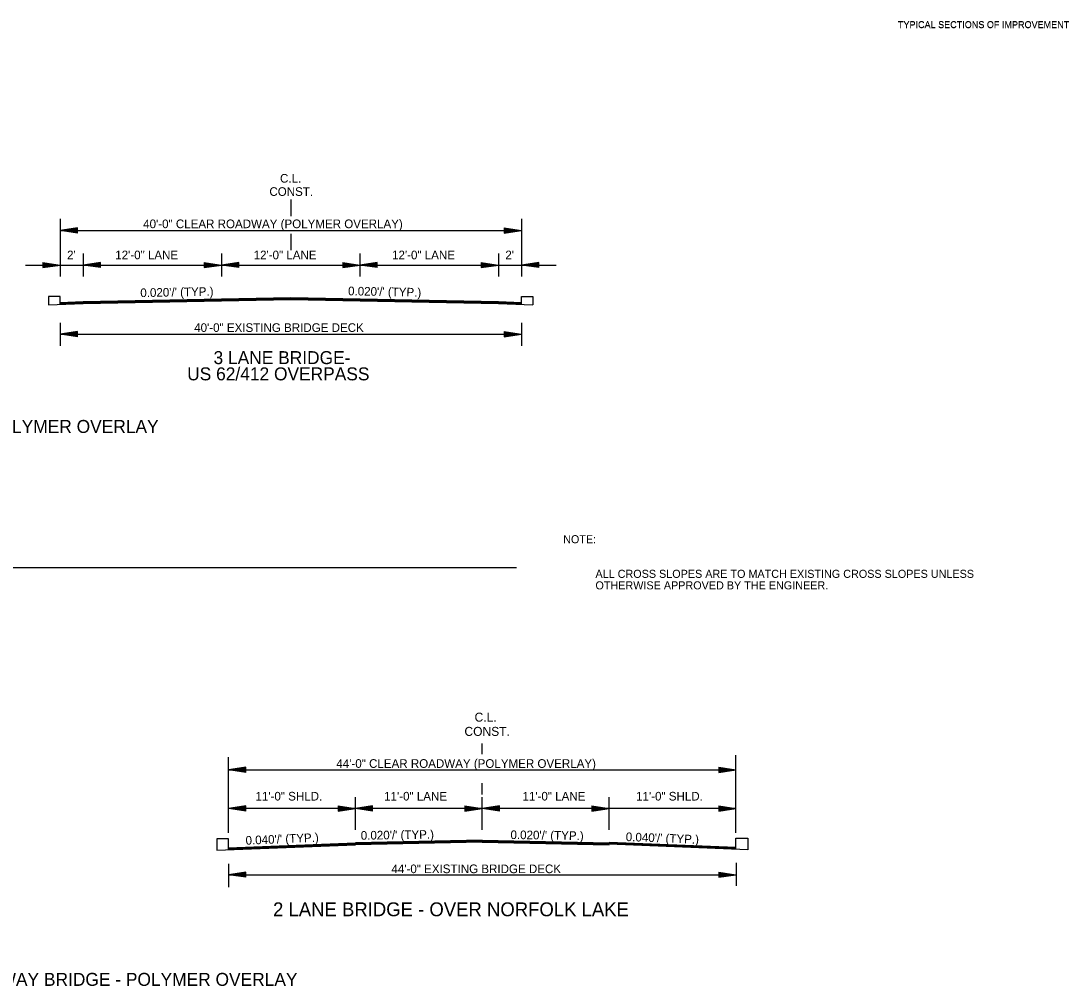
# Model space of a CAD drawing. Extents: x 550980 to 1930787, y -1972975 to 596640.
# Drawn here: x 551625 to 552533, y -1970315 to -1969477 of the extents above; entities that cross this region are included whole.
import ezdxf

# ---------------------------------------------------------------- set-up
doc = ezdxf.new("R2010")
doc.units = 0
for name, color, linetype in [('R_Border', 7, 'Continuous'), ('R_Border Notes', 7, 'Continuous'), ('R_Draft', 7, 'Continuous'), ('S_AREA_CALC', 7, 'Continuous')]:
    doc.layers.add(name, color=color, linetype=linetype)

# ---------------------------------------------------------------- blocks, each defined once
blk = doc.blocks.new('ARROW')
at = {"layer": 'R_Draft'}
for p, q in [((-2, 0.3), (0, 0)), ((-2, 0.3), (-2, -0.3)), ((-2, 0.25), (-0.334, 0)), ((-2, 0.199), (-0.678, 0)), ((-2, 0.149), (-1.011, 0)), ((-2, 0.097), (-1.35, 0)), ((-2, 0.047), (-1.684, 0)), ((-2, -0.3), (0, 0)), ((-2, -0.098), (-1.35, 0)), ((-2, -0.199), (-0.678, 0)), ((-2, -0.25), (-0.334, 0)), ((-2, -0.149), (-1.011, 0)), ((-2, -0.047), (-1.684, 0))]:
    blk.add_line(p, q, dxfattribs=at)

msp = doc.modelspace()

# ---------------------------------------------------------------- linework, layer by layer
at = {"layer": 'R_Border'}
for p, q in [((551858.45, -1969632.14), (551858.45, -1969646.64)), ((551658.45, -1969649.14), (551658.45, -1969699.14)), ((552058.45, -1969649.14), (552058.45, -1969699.14)), ((551658.45, -1969659.14), (552058.45, -1969659.14)), ((551858.45, -1969662.14), (551858.45, -1969676.14)), ((551678.45, -1969679.14), (551678.45, -1969699.14)), ((551798.45, -1969679.14), (551798.45, -1969699.14)), ((551918.45, -1969679.14), (551918.45, -1969699.14)), ((552038.45, -1969679.14), (552038.45, -1969699.14)), ((551628.45, -1969689.14), (552088.45, -1969689.14)), ((551658.45, -1969739.14), (551658.45, -1969759.14)), ((552058.45, -1969739.14), (552058.45, -1969759.14)), ((551658.45, -1969749.14), (552058.45, -1969749.14)), ((550992.91, -1969951.43), (552054.18, -1969951.43)), ((551804.45, -1970186.75), (551794.28, -1970186.75)), ((551794.28, -1970186.75), (551794.28, -1970196.79)), ((551804.45, -1970196.19), (551804.45, -1970186.75)), ((552244.45, -1970195.79), (552244.45, -1970186.35)), ((552244.45, -1970186.35), (552254.62, -1970186.35)), ((552254.62, -1970186.35), (552254.61, -1970196.39))]:
    msp.add_line(p, q, dxfattribs=at)
for points in [[(551658.45, -1969723.04), (551658.45, -1969716.54), (551648.45, -1969716.54), (551648.45, -1969723.74)], [(551648.45, -1969723.74), (551678.45, -1969722.54), (551858.45, -1969718.94), (552038.45, -1969722.54), (552068.45, -1969723.74)], [(551658.45, -1969721.54), (551678.45, -1969720.74), (551858.45, -1969717.14), (552038.45, -1969720.74), (552058.45, -1969721.54)], [(551658.45, -1969721.84), (551678.45, -1969721.04), (551858.45, -1969717.44), (552038.45, -1969721.04), (552058.45, -1969721.84)], [(551658.45, -1969722.14), (551678.45, -1969721.34), (551858.45, -1969717.74), (552038.45, -1969721.34), (552058.45, -1969722.14)], [(551658.45, -1969722.44), (551678.45, -1969721.64), (551858.45, -1969718.04), (552038.45, -1969721.64), (552058.45, -1969722.44)], [(551658.45, -1969722.74), (551678.45, -1969721.94), (551858.45, -1969718.34), (552038.45, -1969721.94), (552058.45, -1969722.74)], [(551658.45, -1969723.04), (551678.45, -1969722.24), (551858.45, -1969718.64), (552038.45, -1969722.24), (552058.45, -1969723.04)], [(552058.45, -1969723.04), (552058.45, -1969716.54), (552068.45, -1969716.54), (552068.45, -1969723.74)]]:
    msp.add_lwpolyline(points, dxfattribs=at)
at = {"layer": 'R_Draft'}
for p, q in [((552024.45, -1970113.53), (552024.45, -1970104.22)), ((551804.45, -1970181.63), (551804.45, -1970116.12)), ((552244.45, -1970181.63), (552244.45, -1970114.36)), ((551819.45, -1970124.69), (551804.45, -1970126.94)), ((551804.45, -1970126.94), (552244.45, -1970126.94)), ((551819.45, -1970129.19), (551804.45, -1970126.94)), ((551819.45, -1970125.07), (551806.96, -1970126.94)), ((551819.45, -1970128.82), (551806.96, -1970126.94)), ((551819.45, -1970125.45), (551809.54, -1970126.94)), ((551819.45, -1970128.43), (551809.54, -1970126.94)), ((551819.45, -1970125.82), (551812.03, -1970126.94)), ((551819.45, -1970128.06), (551812.03, -1970126.94)), ((551819.45, -1970126.21), (551814.58, -1970126.94)), ((551819.45, -1970127.67), (551814.58, -1970126.94)), ((551819.45, -1970126.59), (551817.08, -1970126.94)), ((551819.45, -1970127.29), (551817.08, -1970126.94)), ((551819.45, -1970129.19), (551819.45, -1970124.69)), ((552229.45, -1970124.69), (552244.45, -1970126.94)), ((552229.45, -1970124.69), (552229.45, -1970129.19)), ((552229.45, -1970125.07), (552241.95, -1970126.94)), ((552229.45, -1970125.45), (552239.37, -1970126.94)), ((552229.45, -1970125.82), (552236.87, -1970126.94)), ((552229.45, -1970126.21), (552234.33, -1970126.94)), ((552229.45, -1970126.59), (552231.82, -1970126.94)), ((552229.45, -1970129.19), (552244.45, -1970126.94)), ((552229.45, -1970127.68), (552234.33, -1970126.94)), ((552229.45, -1970128.43), (552239.37, -1970126.94)), ((552229.45, -1970128.82), (552241.95, -1970126.94)), ((552229.45, -1970128.06), (552236.87, -1970126.94)), ((552229.45, -1970127.29), (552231.82, -1970126.94)), ((552024.45, -1970148.46), (552024.45, -1970138.59)), ((551914.45, -1970179.14), (551914.45, -1970150.59)), ((552024.45, -1970179.14), (552024.45, -1970150.59)), ((552134.45, -1970179.14), (552134.45, -1970150.59)), ((551819.45, -1970158.23), (551804.45, -1970160.48)), ((551914.45, -1970160.48), (551804.45, -1970160.48)), ((551819.45, -1970162.73), (551804.45, -1970160.48)), ((551819.45, -1970158.6), (551806.96, -1970160.48)), ((551819.45, -1970162.35), (551806.96, -1970160.48)), ((551819.45, -1970158.99), (551809.54, -1970160.48)), ((551819.45, -1970161.97), (551809.54, -1970160.48)), ((551819.45, -1970159.36), (551812.03, -1970160.48)), ((551819.45, -1970161.6), (551812.03, -1970160.48)), ((551819.45, -1970159.74), (551814.58, -1970160.48)), ((551819.45, -1970161.21), (551814.58, -1970160.48)), ((551819.45, -1970160.13), (551817.08, -1970160.48)), ((551819.45, -1970160.83), (551817.08, -1970160.48)), ((551819.45, -1970162.73), (551819.45, -1970158.23)), ((551899.45, -1970158.23), (551914.45, -1970160.48)), ((551899.45, -1970158.23), (551899.45, -1970162.73)), ((551899.45, -1970158.6), (551911.95, -1970160.48)), ((551899.45, -1970158.99), (551909.37, -1970160.48)), ((551899.45, -1970159.36), (551906.87, -1970160.48)), ((551899.45, -1970159.75), (551904.33, -1970160.48)), ((551899.45, -1970160.13), (551901.82, -1970160.48)), ((551899.45, -1970162.73), (551914.45, -1970160.48)), ((551899.45, -1970161.21), (551904.33, -1970160.48)), ((551899.45, -1970161.97), (551909.37, -1970160.48)), ((551899.45, -1970162.35), (551911.95, -1970160.48)), ((551899.45, -1970161.6), (551906.87, -1970160.48)), ((551899.45, -1970160.83), (551901.82, -1970160.48)), ((551929.45, -1970158.23), (551914.45, -1970160.48)), ((552024.45, -1970160.48), (551914.45, -1970160.48)), ((551929.45, -1970162.73), (551914.45, -1970160.48)), ((551929.45, -1970158.6), (551916.96, -1970160.48)), ((551929.45, -1970162.35), (551916.96, -1970160.48)), ((551929.45, -1970158.99), (551919.54, -1970160.48)), ((551929.45, -1970161.97), (551919.54, -1970160.48)), ((551929.45, -1970159.36), (551922.03, -1970160.48)), ((551929.45, -1970161.6), (551922.03, -1970160.48)), ((551929.45, -1970159.74), (551924.58, -1970160.48)), ((551929.45, -1970161.21), (551924.58, -1970160.48)), ((551929.45, -1970160.13), (551927.08, -1970160.48)), ((551929.45, -1970160.83), (551927.08, -1970160.48)), ((551929.45, -1970162.73), (551929.45, -1970158.23)), ((552009.45, -1970158.23), (552024.45, -1970160.48)), ((552009.45, -1970158.23), (552009.45, -1970162.73)), ((552009.45, -1970158.6), (552021.95, -1970160.48)), ((552009.45, -1970158.99), (552019.37, -1970160.48)), ((552009.45, -1970159.36), (552016.87, -1970160.48)), ((552009.45, -1970159.75), (552014.33, -1970160.48)), ((552009.45, -1970160.13), (552011.82, -1970160.48)), ((552009.45, -1970162.73), (552024.45, -1970160.48)), ((552009.45, -1970161.21), (552014.33, -1970160.48)), ((552009.45, -1970161.97), (552019.37, -1970160.48)), ((552009.45, -1970162.35), (552021.95, -1970160.48)), ((552009.45, -1970161.6), (552016.87, -1970160.48)), ((552009.45, -1970160.83), (552011.82, -1970160.48)), ((552039.45, -1970158.23), (552024.45, -1970160.48)), ((552134.45, -1970160.48), (552024.45, -1970160.48)), ((552039.45, -1970162.73), (552024.45, -1970160.48)), ((552039.45, -1970158.6), (552026.96, -1970160.48)), ((552039.45, -1970162.35), (552026.96, -1970160.48)), ((552039.45, -1970158.99), (552029.54, -1970160.48)), ((552039.45, -1970161.97), (552029.54, -1970160.48)), ((552039.45, -1970159.36), (552032.03, -1970160.48)), ((552039.45, -1970161.6), (552032.03, -1970160.48)), ((552039.45, -1970159.74), (552034.58, -1970160.48)), ((552039.45, -1970161.21), (552034.58, -1970160.48)), ((552039.45, -1970160.13), (552037.08, -1970160.48)), ((552039.45, -1970160.83), (552037.08, -1970160.48)), ((552039.45, -1970162.73), (552039.45, -1970158.23)), ((552119.45, -1970158.23), (552134.45, -1970160.48)), ((552119.45, -1970158.23), (552119.45, -1970162.73)), ((552119.45, -1970158.6), (552131.95, -1970160.48)), ((552119.45, -1970158.99), (552129.37, -1970160.48)), ((552119.45, -1970159.36), (552126.87, -1970160.48)), ((552119.45, -1970159.75), (552124.33, -1970160.48)), ((552119.45, -1970160.13), (552121.82, -1970160.48)), ((552119.45, -1970162.73), (552134.45, -1970160.48)), ((552119.45, -1970161.21), (552124.33, -1970160.48)), ((552119.45, -1970161.97), (552129.37, -1970160.48)), ((552119.45, -1970162.35), (552131.95, -1970160.48)), ((552119.45, -1970161.6), (552126.87, -1970160.48)), ((552119.45, -1970160.83), (552121.82, -1970160.48)), ((552244.45, -1970160.48), (552134.45, -1970160.48)), ((552229.45, -1970158.23), (552244.45, -1970160.48)), ((552229.45, -1970158.23), (552229.45, -1970162.73)), ((552229.45, -1970158.6), (552241.95, -1970160.48)), ((552229.45, -1970158.99), (552239.37, -1970160.48)), ((552229.45, -1970159.36), (552236.87, -1970160.48)), ((552229.45, -1970159.75), (552234.33, -1970160.48)), ((552229.45, -1970160.13), (552231.82, -1970160.48)), ((552229.45, -1970162.73), (552244.45, -1970160.48)), ((552229.45, -1970161.21), (552234.33, -1970160.48)), ((552229.45, -1970161.97), (552239.37, -1970160.48)), ((552229.45, -1970162.35), (552241.95, -1970160.48)), ((552229.45, -1970161.6), (552236.87, -1970160.48)), ((552229.45, -1970160.83), (552231.82, -1970160.48)), ((551794.28, -1970196.79), (551914.45, -1970191.99)), ((551804.45, -1970194.69), (551914.45, -1970190.29)), ((551804.45, -1970194.99), (551914.45, -1970190.59)), ((551804.45, -1970195.29), (551914.45, -1970190.89)), ((551804.45, -1970195.59), (551914.45, -1970191.19)), ((551804.45, -1970195.89), (551914.45, -1970191.49)), ((551804.45, -1970196.19), (551914.45, -1970191.79)), ((552024.45, -1970188.09), (551914.45, -1970190.29)), ((552024.46, -1970188.39), (551914.45, -1970190.59)), ((552024.46, -1970188.69), (551914.45, -1970190.89)), ((552024.47, -1970188.99), (551914.45, -1970191.19)), ((552024.48, -1970189.29), (551914.45, -1970191.49)), ((552024.48, -1970189.58), (551914.45, -1970191.79)), ((552024.49, -1970189.78), (551914.45, -1970191.99)), ((552024.42, -1970189.58), (552134.45, -1970191.79)), ((552024.42, -1970189.78), (552134.45, -1970191.99)), ((552024.43, -1970188.99), (552134.45, -1970191.19)), ((552024.43, -1970189.29), (552134.45, -1970191.49)), ((552024.44, -1970188.69), (552134.45, -1970190.89)), ((552024.45, -1970188.09), (552134.45, -1970190.29)), ((552024.45, -1970188.39), (552134.45, -1970190.59)), ((552244.45, -1970194.29), (552134.45, -1970189.89)), ((552244.45, -1970194.59), (552134.45, -1970190.19)), ((552244.45, -1970194.89), (552134.45, -1970190.49)), ((552244.45, -1970195.19), (552134.45, -1970190.79)), ((552244.45, -1970195.49), (552134.45, -1970191.09)), ((552244.45, -1970195.79), (552134.45, -1970191.39)), ((552254.61, -1970196.39), (552134.45, -1970191.59)), ((551804.47, -1970208.66), (551804.47, -1970228.66)), ((552244.56, -1970207.69), (552244.56, -1970227.69)), ((551819.45, -1970215.69), (551804.45, -1970217.94)), ((551804.45, -1970217.94), (552244.45, -1970217.94)), ((551819.45, -1970220.19), (551804.45, -1970217.94)), ((551819.45, -1970216.07), (551806.96, -1970217.94)), ((551819.45, -1970219.82), (551806.96, -1970217.94)), ((551819.45, -1970216.45), (551809.54, -1970217.94)), ((551819.45, -1970219.44), (551809.54, -1970217.94)), ((551819.45, -1970216.83), (551812.03, -1970217.94)), ((551819.45, -1970219.06), (551812.03, -1970217.94)), ((551819.45, -1970217.21), (551814.58, -1970217.94)), ((551819.45, -1970218.67), (551814.58, -1970217.94)), ((551819.45, -1970217.59), (551817.08, -1970217.94)), ((551819.45, -1970218.3), (551817.08, -1970217.94)), ((551819.45, -1970220.19), (551819.45, -1970215.69)), ((552229.45, -1970215.69), (552244.45, -1970217.94)), ((552229.45, -1970215.69), (552229.45, -1970220.19)), ((552229.45, -1970216.07), (552241.95, -1970217.94)), ((552229.45, -1970216.45), (552239.37, -1970217.94)), ((552229.45, -1970216.83), (552236.87, -1970217.94)), ((552229.45, -1970217.22), (552234.33, -1970217.94)), ((552229.45, -1970217.59), (552231.82, -1970217.94)), ((552229.45, -1970220.19), (552244.45, -1970217.94)), ((552229.45, -1970218.68), (552234.33, -1970217.94)), ((552229.45, -1970219.44), (552239.37, -1970217.94)), ((552229.45, -1970219.82), (552241.95, -1970217.94)), ((552229.45, -1970219.06), (552236.87, -1970217.94)), ((552229.45, -1970218.3), (552231.82, -1970217.94))]:
    msp.add_line(p, q, dxfattribs=at)

# ---------------------------------------------------------------- block references
at = {"layer": 'R_Border', "xscale": 7.5, "yscale": 7.5, "rotation": 180}
for p in [(551658.45, -1969659.14), (551678.45, -1969689.14), (551798.45, -1969689.14), (551918.45, -1969689.14), (552058.45, -1969689.14), (551658.45, -1969749.14)]:
    msp.add_blockref('ARROW', p, dxfattribs=at)
at = {"layer": 'R_Border', "xscale": 7.5, "yscale": 7.5}
for p in [(552058.45, -1969659.14), (551658.45, -1969689.14), (551798.45, -1969689.14), (551918.45, -1969689.14), (551918.45, -1969689.14), (552038.45, -1969689.14), (552058.45, -1969749.14)]:
    msp.add_blockref('ARROW', p, dxfattribs=at)

# ---------------------------------------------------------------- texts
at = {"layer": 'R_Border'}
for s, height, p in [('C.L.', 7.5, (551849.12, -1969617.64)), ('CONST.', 7.5, (551839.91, -1969629.14)), ('40\'-0" CLEAR ROADWAY (POLYMER OVERLAY)', 7.5, (551730.48, -1969657.14)), ("2'", 7.5, (551664.5, -1969684.14)), ('12\'-0" LANE', 7.5, (551706.27, -1969684.14)), ('12\'-0" LANE', 7.5, (551826.27, -1969684.14)), ('12\'-0" LANE', 7.5, (551946.27, -1969684.14)), ("2'", 7.5, (552044.5, -1969684.14)), ('40\'-0" EXISTING BRIDGE DECK', 7.5, (551774.71, -1969747.14)), ('3 LANE BRIDGE-', 11.25, (551791.49, -1969775.06)), ('US 62/412 OVERPASS', 11.25, (551768.63, -1969789.14)), ('40 FT. CLEAR ROADWAY BRIDGE - POLYMER OVERLAY', 11.25, (551340.09, -1969834.77))]:
    msp.add_text(s, height=height, dxfattribs=at).set_placement(p)
for rotation, p in [(1.1458, (551728.07, -1969716.95)), (358.8542, (551908.07, -1969715.33))]:
    msp.add_text("0.020'/' (TYP.)", height=7.5, rotation=rotation, dxfattribs=at).set_placement(p)
at = {"layer": 'R_Border Notes'}
for s, p in [('NOTE: ', (552094.62, -1969930.47)), ('ALL CROSS SLOPES ARE TO MATCH EXISTING CROSS SLOPES UNLESS ', (552122.62, -1969960.47)), ('OTHERWISE APPROVED BY THE ENGINEER.', (552122.62, -1969970.47))]:
    msp.add_text(s, height=7, dxfattribs=at).set_placement(p)
at = {"layer": 'R_Draft'}
for s, height, p in [('C.L.', 7.8, (552017.81, -1970085.19)), ('CONST.', 7.8, (552009.03, -1970097.55)), ('44\'-0" CLEAR ROADWAY (POLYMER OVERLAY)', 7.5, (551897.99, -1970125.27)), ('11\'-0" SHLD.', 7.5, (551827.86, -1970153.62)), ('11\'-0" LANE', 7.5, (551939.39, -1970153.62)), ('11\'-0" LANE', 7.5, (552059.36, -1970153.62)), ('11\'-0" SHLD.', 7.5, (552157.86, -1970153.62)), ('44\'-0" EXISTING BRIDGE DECK', 7.5, (551945.73, -1970216.62)), ('2 LANE BRIDGE - OVER NORFOLK LAKE', 12, (551843.09, -1970253.98)), ('44 FT. CLEAR ROADWAY BRIDGE - POLYMER OVERLAY', 11.25, (551460.51, -1970314.38))]:
    msp.add_text(s, height=height, dxfattribs=at).set_placement(p)
for s, rotation, p in [("0.040'/' (TYP.)", 2.44797, (551819.42, -1970192.01)), ("0.020'/' (TYP.)", 0.87191, (551919.18, -1970187.65)), ("0.020'/' (TYP.)", 359.16404, (552048.9, -1970186.99)), ("0.040'/' (TYP.)", 357.81683, (552148.8, -1970188.74))]:
    msp.add_text(s, height=7.5, rotation=rotation, dxfattribs=at).set_placement(p)
at = {"layer": 'S_AREA_CALC'}
for p in [(552384.89, -1969483.35), (552384.89, -1969483.7)]:
    msp.add_text('TYPICAL SECTIONS OF IMPROVEMENT', height=5.862, rotation=360, dxfattribs=at).set_placement(p)

doc.saveas('drawing.dxf')
